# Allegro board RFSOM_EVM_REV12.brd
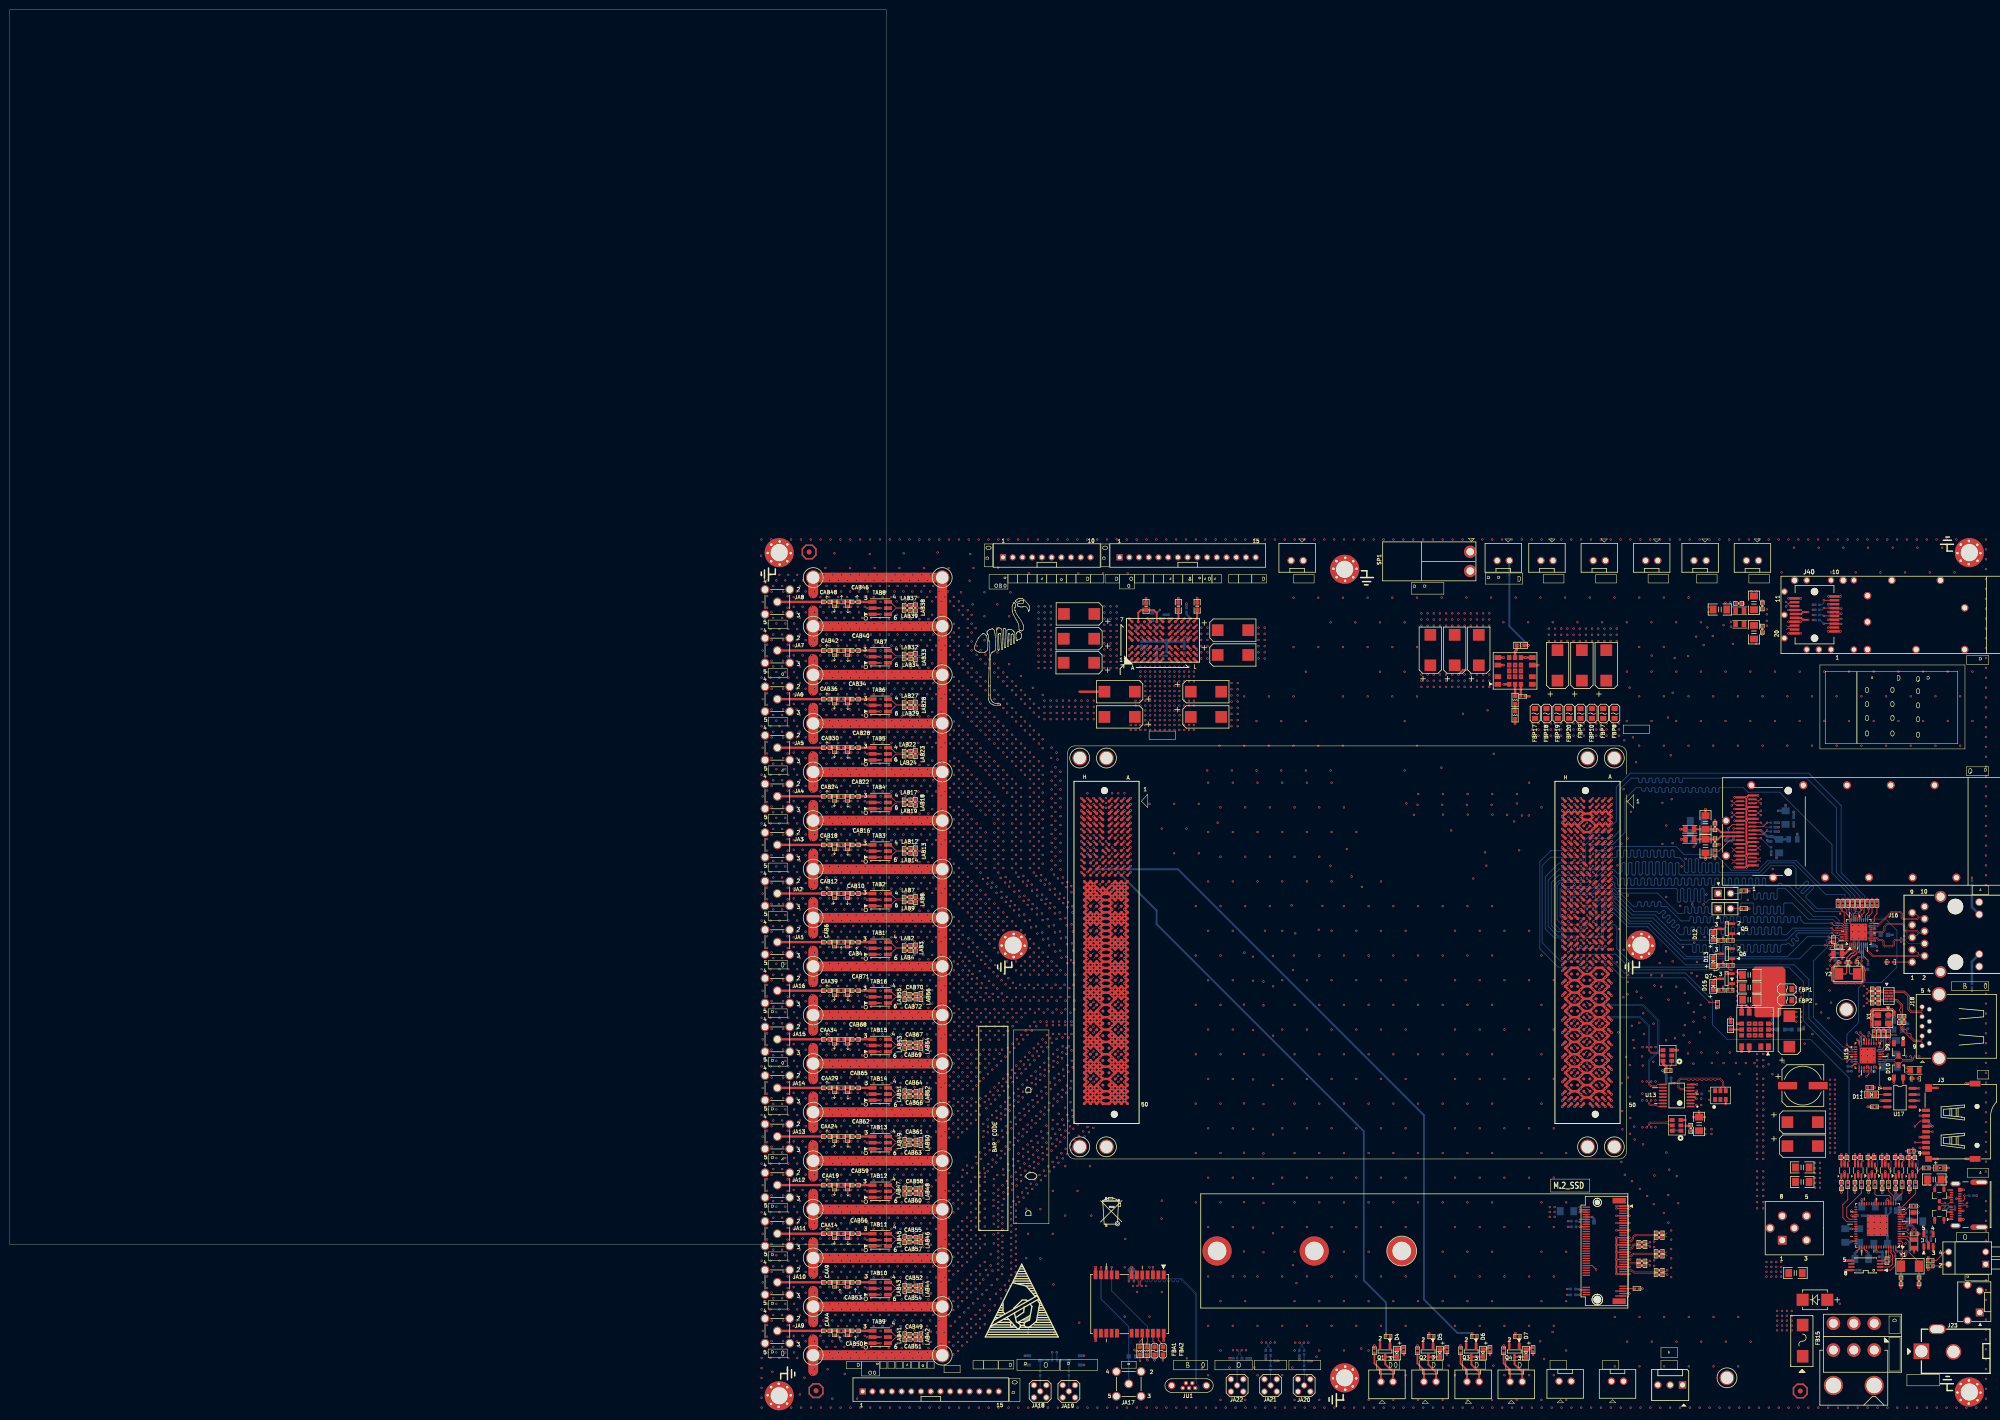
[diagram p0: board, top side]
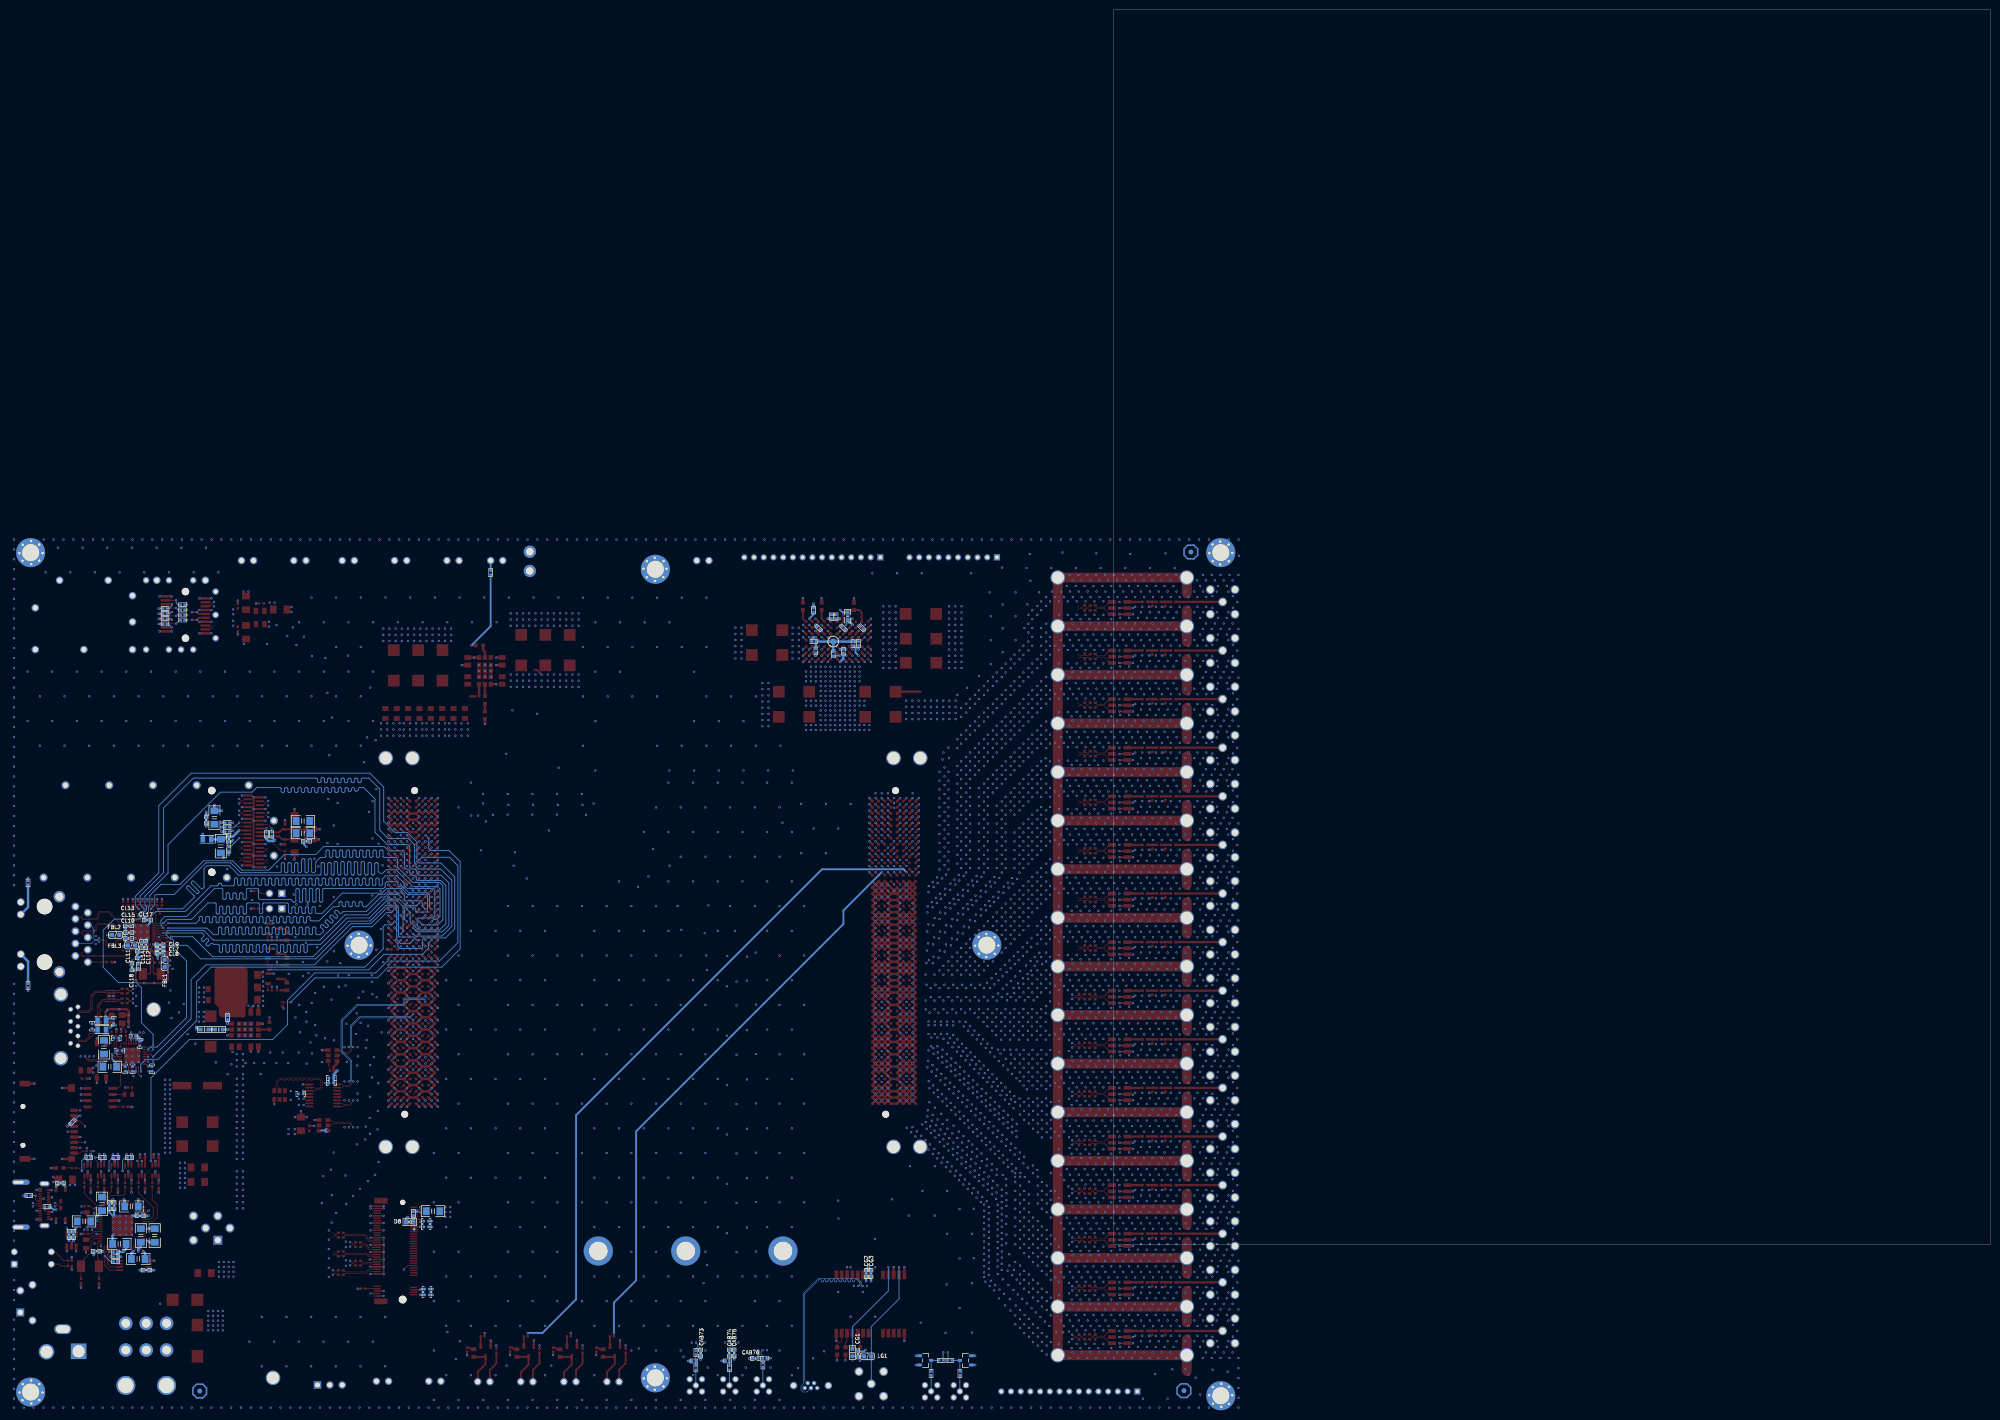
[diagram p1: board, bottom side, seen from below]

Outline 180.34 x 254 mm; copper layers: TOP, GND02, ART03, GND04, ART05, GND06, POWER07, POWER08, GND09, ART10, GND11, BOTTOM. Coordinates in mm from the lower left corner of the outline.
Outline path: 0,254 180.34,254 180.34,0 0,0 0,254

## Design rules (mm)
constraint set DEFAULT: min track width 0.173
net group BANK128_MGT_CLK1: nets BANK128_MGT_CLK1_N BANK128_MGT_CLK1_P
net group BANK128_MGT_RX0_: nets BANK128_MGT_RX0_N BANK128_MGT_RX0_P
net group BANK128_MGT_RX1_: nets BANK128_MGT_RX1_N BANK128_MGT_RX1_P
net group BANK128_MGT_RX2_: nets BANK128_MGT_RX2_N BANK128_MGT_RX2_P
net group BANK128_MGT_RX3_: nets BANK128_MGT_RX3_N BANK128_MGT_RX3_P
net group BANK128_MGT_TX0_: nets BANK128_MGT_TX0_N BANK128_MGT_TX0_P
net group BANK128_MGT_TX1_: nets BANK128_MGT_TX1_N BANK128_MGT_TX1_P
net group BANK128_MGT_TX2_: nets BANK128_MGT_TX2_N BANK128_MGT_TX2_P
net group BANK128_MGT_TX3_: nets BANK128_MGT_TX3_N BANK128_MGT_TX3_P
net group BANK129_MGT_RX0_: nets BANK129_MGT_RX0_N BANK129_MGT_RX0_P
net group BANK129_MGT_TX0_: nets BANK129_MGT_TX0_N BANK129_MGT_TX0_P
net group BANK505_MGT_CLK0_: nets BANK505_MGT_CLK0_N BANK505_MGT_CLK0_P
net group BANK505_MGT_CLK2_: nets BANK505_MGT_CLK2_N BANK505_MGT_CLK2_P
net group BANK505_MGT_RX0_N: nets BANK505_MGT_RX0_N N2236203120
net group BANK505_MGT_RX0_P: nets BANK505_MGT_RX0_P N2236203121
net group BANK505_MGT_RX1_N: nets BANK505_MGT_RX1_N N2236203114
net group BANK505_MGT_RX1_P: nets BANK505_MGT_RX1_P N2236203115
net group BANK505_MGT_TX0_N: nets BANK505_MGT_TX0_N N2236203123
net group BANK505_MGT_TX0_P: nets BANK505_MGT_TX0_P N2236203124
net group BANK505_MGT_TX1_N: nets BANK505_MGT_TX1_N N2236203117
net group BANK505_MGT_TX1_P: nets BANK505_MGT_TX1_P N2236203118
net group CLK_100M_: nets CLK_100M_N CLK_100M_P
net group CLKIN0_: nets CLKIN0_N CLKIN0_P
net group DIFFPAIR11: nets N22696463 N22696580
net group DIFFPAIR12: nets N22696156 N22696283
net group DIFFPAIR13: nets N22697841 N22697954
net group DIFFPAIR14: nets N22697544 N22697657
net group DIFFPAIR15: nets N22699217 N22699330
net group DIFFPAIR16: nets N22698936 N22699049
net group DIFFPAIR17: nets N22700663 N22700802
net group DIFFPAIR18: nets N22700324 N22700437
net group DIFFPAIR19: nets N22692224 N22692315
net group DIFFPAIR20: nets N22692505 N22692596
net group DIFFPAIR21: nets N22693543 N22693634
net group DIFFPAIR22: nets N22693824 N22693915
net group DIFFPAIR23: nets N22694836 N22694927
net group DIFFPAIR24: nets N22545864 N22545955
net group DIFFPAIR25: nets N22695117 N22695208
net group DIFFPAIR26: nets N22546147 N22546240
net group DU: nets DU+ DU-
net group GPS_USB_D: nets GPS_USB_DN GPS_USB_DP
net group M2_DEV_CLKN: nets M2_DEV_CLKN N223618380
net group M2_DEV_CLKP: nets M2_DEV_CLKP N223618460
net group N22536481: nets N22536481 N22536506
net group RX_00: nets RX_00_N RX_00_P
net group RX_01: nets RX_01_N RX_01_P
net group RX_02: nets RX_02_N RX_02_P
net group RX_03: nets RX_03_N RX_03_P
net group RX_04: nets RX_04_N RX_04_P
net group RX_05: nets RX_05_N RX_05_P
net group RX_06: nets RX_06_N RX_06_P
net group RX_07: nets RX_07_N RX_07_P
net group SYS_CLK_OUT_: nets SYS_CLK_OUT_N SYS_CLK_OUT_P
net group SYSREF_IN_: nets SYSREF_IN_N SYSREF_IN_P
net group TX_00: nets TX_00_N TX_00_P
net group TX_01: nets TX_01_N TX_01_P
net group TX_02: nets TX_02_N TX_02_P
net group TX_03: nets TX_03_N TX_03_P
net group TX_04: nets TX_04_N TX_04_P
net group TX_05: nets TX_05_N TX_05_P
net group TX_06: nets TX_06_N TX_06_P
net group TX_07: nets TX_07_N TX_07_P
net group +1.8V: nets N22536187
net group POWER: nets ZQSFP_VCC ZQSFP_VCCRX ZQSFP_VCCTX
net group RF: nets N22545929 N22545941 N22545947 N22545953 N22546214 N22546226 N22546232 N22546238 N22692289 N22692291 N22692307 N22692313 N22692570 N22692582 N22692588 N22692594 N22693600 N22693620 N22693626 N22693632 N22693889 N22693901 N22693907 N22693913 N22694901 N22694903 N22694919 N22694925 N22695182 N22695184 N22695200 N22695206 N22696251 N22696263 N22696269 N22696275 N22696550 N22696562 N22696568 N22696574 N22697619 N22697639 N22697645 N22697651 N22697916 N22697918 N22697942 N22697948 N22699019 N22699033 N22699037 N22699043 N22699300 N22699302 N22699318 N22699324 N22700407 N22700409 N22700425 N22700431 N22700760 N22700762 N22700790 N22700796
net group USB_90: nets BANK505_MGT_RX2_N BANK505_MGT_RX2_P BANK505_MGT_TX2_N BANK505_MGT_TX2_P N223630967 N223630968 USB_DM USB_DP USB_RX_N USB_RX_P USB_TX_N USB_TX_P

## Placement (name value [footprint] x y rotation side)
C1  0.1uF/25V/X7R/10%  [C0402]  382.48 12.04 270 top
C2  0.1uF/25V/X7R/10%  [C0402]  382.98 17.81 0 top
C3  0.1uF/25V/X7R/10%  [C0402]  390.86 12.04 270 top
C4  0.1uF/25V/X7R/10%  [C0402]  391.37 17.81 0 top
C5  0.1uF/25V/X7R/10%  [C0402]  388.06 12.04 270 top
C6  0.1uF/25V/X7R/10%  [C0402]  388.57 17.81 0 top
C7  0.1uF/25V/X7R/10%  [C0402]  385.27 12.04 270 top
C8  0.1uF/25V/X7R/10%  [C0402]  385.78 17.81 0 top
C9  47uF/6.3V/X5R/20%  [C1206]  380.54 1.78 90 bottom
C10  47uF/6.3V/X5R/20%  [C1206]  384.96 0.05 0 bottom
C11  18PF/25V/X5R/20%  [C0402]  389.15 -7.57 270 top
C12  0.1uF/25V/X7R/10%  [C0402]  379.68 12.04 270 top
C13  0.1uF/25V/X7R/10%  [C0402]  380.19 17.81 0 top
C14  18PF/25V/X5R/20%  [C0402]  392.86 -7.57 270 top
C15  22UF/25V/X5R/20%  [C1206]  396.01 13.31 0 top
C16  0.47uF/6.3V/X5R/20%  [C0402]  397.05 12.57 0 bottom
C17  0.1uF/25V/X7R/10%  [C0402]  376.89 12.04 270 top
C18  0.1uF/25V/X7R/10%  [C0402]  377.4 17.81 0 top
C19  47uF/6.3V/X5R/20%  [C1206]  382.47 7.75 0 bottom
C20  47uF/6.3V/X5R/20%  [C1206]  377.7 1.78 270 bottom
C21  47uF/6.3V/X5R/20%  [C0402]  387.02 7.9 270 bottom
C22  47uF/6.3V/X5R/20%  [C0402]  386.05 7.9 270 bottom
C23  22UF/25V/X5R/20%  [C1206]  392.23 4.68 180 bottom
C24  0.47uF/6.3V/X5R/20%  [C0402]  394.41 1.98 270 bottom
C25  47uF/6.3V/X5R/20%  [C1206]  388.54 8.28 90 bottom
C26  47uF/6.3V/X5R/20%  [C1206]  381.08 -3.05 0 bottom
C27  4.7uF/6.3V/X5R/20%  [C0402]  389.69 -1.47 0 bottom
C28  0.47uF/6.3V/X5R/20%  [C0402]  380.7 5.86 0 bottom
C29  0.1uF/25V/X7R/10%  [C0402]  395.33 1.98 270 bottom
C30  0.47uF/10V/X5R/20%  [C0402]  379.45 -5.35 0 bottom
C31  22uF/25V,X5R/20%  [C1206]  347.19 84.56 0 bottom
C32  0.1uF/25V/,X7R/10%  [C0402]  346.48 82.88 0 bottom
C33  22uF/25V,X5R/20%  [C1206]  348.93 81.89 270 top
C34  0.1uF/25V/,X7R/10%  [C0402]  350.88 82.78 270 top
C35  22uF/25V,X5R/20%  [C1206]  364.08 81.9 270 bottom
C36  0.1uF/25V/,X7R/10%  [C0402]  362.43 83.36 270 bottom
C37  22uF/25V,X5R/20%  [C1206]  348.93 86.77 90 top
C38  0.1uF/25V/,X7R/10%  [C0402]  350.88 85.88 90 top
C39  22uF/25V,X5R/20%  [C1206]  365.4 87.77 90 bottom
C40  0.1uF/25V/,X7R/10%  [C0402]  367.08 87.26 90 bottom
C41  22uF/25V,X5R/20%  [C1206]  347.6 24.73 90 top
C42  0.1uF/25V/,X7R/10%  [C0402]  345.89 23.84 90 top
C43  22uF/25V,X5R/20%  [C1206]  351.89 130.58 180 top
C44  0.1uF/25V/,X7R/10%  [C0402]  355.75 131.83 0 top
C45  22uF/25V,X5R/20%  [C1206]  358.9 131.96 90 top
C46  0.1uF/25V/,X7R/10%  [C0402]  360.61 131.32 90 top
C47  22uF/25V,X5R/20%  [C1206]  358.9 125.91 270 top
C48  0.1uF/25V/,X7R/10%  [C0402]  360.61 126.54 270 top
C53  CAP,0.1UF,DC25V,0402,X5R  [C0402-BGA]  387.06 58.03 180 top
C57  CAP,27pF,DC25V,0402,X5R  [C0402-BGA]  379.36 57.9 180 top
C58  CAP,27pF,DC25V,0402,X5R  [C0402-BGA]  377.18 57.92 0 top
C68  0.1uF/25V/X7R/10%  [C0402]  339.39 2.31 0 top
C69  0.1uF/25V/X7R/10%  [C0402]  339.39 1.37 0 top
C70  0.1uF/25V/X7R/10%  [C0402]  335.84 0.39 0 top
C71  0.1uF/25V/X7R/10%  [C0402]  335.84 -0.55 0 top
C72  0.1uF/25V/X7R/10%  [C0402]  339.39 -1.53 0 top
C73  0.1uF/25V/X7R/10%  [C0402]  339.39 -2.47 0 top
C74  0.1uF/25V/X7R/10%  [C0402]  335.84 -3.46 0 top
C75  0.1uF/25V/X7R/10%  [C0402]  335.84 -4.4 0 top
C76  0.1uF/25V/X7R/10%  [C0402]  339.39 -5.38 0 top
C77  0.1uF/25V/X7R/10%  [C0402]  339.39 -6.32 0 top
C78  0.1uF/25V/,X7R/10%  [C0402-BGA]  347.63 30.91 180 bottom
C79  10uF/25V/X5R/20%  [C1206]  347.19 87.07 0 bottom
C80  0.1uF/25V/,X7R/10%  [C0402-BGA]  321.67 -10.44 180 bottom
C81  0.1uF/25V/,X7R/10%  [C0402-BGA]  321.67 -9.25 180 bottom
C84  0.1uF/25V/,X7R/10%  [C1206]  320.42 6.78 180 bottom
C85  0.1uF/25V/,X7R/10%  [C0402-BGA]  321.84 3.56 180 bottom
C86  0.1uF/25V/,X7R/10%  [C0402-BGA]  321.84 4.72 180 bottom
C87  0.1uF/25V/,X7R/10%  [C0402-BGA]  390.56 44.85 90 bottom
C88  0.1uF/25V/,X7R/10%  [C0402]  389.78 46.23 270 top
C89  0.1uF/25V/,X7R/10%  [C0402]  388.8 46.23 270 top
C90  4.7UF/25V/X5R/20%  [C1206]  386.94 36.5 0 bottom
C91  0.1uF/25V/,X7R/10%  [C0402-BGA]  392.18 34.06 180 top
C92  0.1uF/25V/,X7R/10%  [C0402]  383.87 52.53 180 top
C93  10uF/25V/X5R/10%  [C1206]  388.14 40.51 270 bottom
C94  0.1uF/25V/,X7R/10%  [C0402-BGA]  385.6 42.44 180 bottom
C95  0.1uF/25V/,X7R/10%  [C0402]  383.87 51.59 180 top
C96  0.1uF/25V/,X7R/10%  [C0402]  383.87 49.58 180 top
C97  0.1uF/25V/,X7R/10%  [C0402]  383.87 50.52 180 top
C98  0.47UF/25V/X5R/10%  [C0402-BGA]  386.13 45.9 90 bottom
C101  0.1uF/25V/,X7R/10%  [C0402-BGA]  380.8 41.3 270 bottom
C102  0.1uF/25V/,X7R/10%  [C0402-BGA]  382.27 36.07 90 bottom
C103  0.1uF/25V/,X7R/10%  [C0402-BGA]  378.21 36.08 270 bottom
C104  0.1uF/25V/,X7R/10%  [C0402-BGA]  383.74 36.06 90 bottom
C105  100pF/10V/X5R/20%  [C0603]  233.82 131.22 90 top
C106  100pF/10V/X5R/20%  [C0603]  240.46 131.24 90 top
C107  100pF/10V/X5R/20%  [C0603]  244.33 131.24 90 top
C108  22UF/25V/X5R/20%  [C1206]  367.44 -5.94 0 top
C109  22UF/25V/X5R/20%  [C1206]  368.83 12.8 0 top
C110  22UF/25V/X5R/20%  [C1206]  368.83 15.79 0 top
C288  1uF/25V/,X5R/10%  [C0402-BGA]  341.34 33.11 0 bottom
C289  0.1uF/25V/,X7R/10%  [C0402-BGA]  341.34 34.2 0 bottom
C290  0.1uF/25V/,X7R/10%  [C0402-BGA]  384.88 39.82 180 bottom
CAA4  0.1uF/25V/X7R/10%  [0402C]  168.1 -17.85 0 top
CAA9  0.1uF/25V/X7R/10%  [0402C]  168.1 -7.85 0 top
CAA14  0.1uF/25V/X7R/10%  [0402C]  168.1 2.15 0 top
CAA19  0.1uF/25V/X7R/10%  [0402C]  168.1 12.15 0 top
CAA24  0.1uF/25V/X7R/10%  [0402C]  168.1 22.15 0 top
CAA29  0.1uF/25V/X7R/10%  [0402C]  168.1 32.15 0 top
CAA34  0.1uF/25V/X7R/10%  [0402C]  168.1 42.15 0 top
CAA39  0.1uF/25V/X7R/10%  [0402C]  168.1 52.15 0 top
CAB4  0.1uF/25V/X7R/10%  [0402C]  173.97 62.15 180 top
CAB6  0.1uF/25V/X7R/10%  [0402C]  168.1 62.15 180 top
CAB10  0.1uF/25V/X7R/10%  [0402C]  173.97 72.15 180 top
CAB12  0.1uF/25V/X7R/10%  [0402C]  168.1 72.15 180 top
CAB16  0.1uF/25V/X7R/10%  [0402C]  173.97 82.15 180 top
CAB18  0.1uF/25V/X7R/10%  [0402C]  168.1 82.15 180 top
CAB22  0.1uF/25V/X7R/10%  [0402C]  173.97 92.15 180 top
CAB24  0.1uF/25V/X7R/10%  [0402C]  168.1 92.15 180 top
CAB28  0.1uF/25V/X7R/10%  [0402C]  173.97 102.15 180 top
CAB30  0.1uF/25V/X7R/10%  [0402C]  168.1 102.15 180 top
CAB34  0.1uF/25V/X7R/10%  [0402C]  173.97 112.15 180 top
CAB36  0.1uF/25V/X7R/10%  [0402C]  168.1 112.15 180 top
CAB40  0.1uF/25V/X7R/10%  [0402C]  173.97 122.15 180 top
CAB42  0.1uF/25V/X7R/10%  [0402C]  168.1 122.15 180 top
CAB46  0.1uF/25V/X7R/10%  [0402C]  173.97 132.15 180 top
CAB48  0.1uF/25V/X7R/10%  [0402C]  168.1 132.15 180 top
CAB49  0.1uF/25V/X7R/10%  [0402C]  185.83 -18.57 180 top
CAB50  0.1uF/25V/X7R/10%  [0402C]  173.97 -17.85 180 top
CAB51  0.1uF/25V/X7R/10%  [0402C]  185.83 -19.59 180 top
CAB52  0.1uF/25V/X7R/10%  [0402C]  185.83 -8.57 180 top
CAB53  0.1uF/25V/X7R/10%  [0402C]  173.97 -7.85 180 top
CAB54  0.1uF/25V/X7R/10%  [0402C]  185.83 -9.59 180 top
CAB55  0.1uF/25V/X7R/10%  [0402C]  185.83 1.43 180 top
CAB56  0.1uF/25V/X7R/10%  [0402C]  173.97 2.15 180 top
CAB57  0.1uF/25V/X7R/10%  [0402C]  185.83 0.41 180 top
CAB58  0.1uF/25V/X7R/10%  [0402C]  185.83 11.43 180 top
CAB59  0.1uF/25V/X7R/10%  [0402C]  173.97 12.15 180 top
CAB60  0.1uF/25V/X7R/10%  [0402C]  185.83 10.41 180 top
CAB61  0.1uF/25V/X7R/10%  [0402C]  185.83 21.43 180 top
CAB62  0.1uF/25V/X7R/10%  [0402C]  173.97 22.15 180 top
CAB63  0.1uF/25V/X7R/10%  [0402C]  185.83 20.41 180 top
CAB64  0.1uF/25V/X7R/10%  [0402C]  185.83 31.43 180 top
CAB65  0.1uF/25V/X7R/10%  [0402C]  173.97 32.15 180 top
CAB66  0.1uF/25V/X7R/10%  [0402C]  185.83 30.41 180 top
CAB67  0.1uF/25V/X7R/10%  [0402C]  185.83 41.43 180 top
CAB68  0.1uF/25V/X7R/10%  [0402C]  173.97 42.15 180 top
CAB69  0.1uF/25V/X7R/10%  [0402C]  185.83 40.41 180 top
CAB70  0.1uF/25V/X7R/10%  [0402C]  185.83 51.43 180 top
CAB71  0.1uF/25V/X7R/10%  [0402C]  173.97 52.15 180 top
CAB72  0.1uF/25V/X7R/10%  [0402C]  185.83 50.41 180 top
CAB73  0.1uF/25V/X7R/10%  [0402C]  265.35 -22.42 90 bottom
CAB74  0.1uF/25V/X7R/10%  [0402C]  259.45 -22.4 90 bottom
CAB75  0.1uF/25V/X7R/10%  [0402C]  258.46 -22.4 90 bottom
CAB76  0.1uF/25V/X7R/10%  [0402C]  254.05 -23.52 180 bottom
CG1  0.01uF/16V/X5R/20%  [0402C]  233 -22.58 90 bottom
CG2  0.1uF/25V/,X7R/10%  [0402C]  231.32 -6.03 270 bottom
CG3  47pF/16V/X7R/20%  [0402C]  230.3 -6.03 270 bottom
CIN1  22uF/25V/X5R/20%  [7343-43]  220 119.63 180 top
CIN2  22uF/25V/X5R/20%  [7343-43]  220.01 124.57 180 top
CIN3  22uF/25V/X5R/20%  [7343-43]  220.05 129.68 180 top
CIN4  22uF/25V/X5R/20%  [7343-43]  251.69 126.34 0 top
CIN5  100uF/25V/X5R/20%  [7343-43]  251.69 121.23 0 top
CIN6  22uF/25V/X5R/20%  [7343-43]  368.91 20.17 0 top
CIN7  22uF/25V/X5R/20%  [7343-43]  366.18 43.76 90 top
CIN8  22uF/25V/X5R/20%  [7343-43]  368.91 25.1 0 top
CIN9  22uF/25V/X5R/20%  [7343-43]  297.31 122.23 90 top
CIN10  22uF/25V/X5R/20%  [7343-43]  302.28 122.23 90 top
CIN11  22uF/25V/X5R/20%  [7343-43]  292.31 122.23 90 top
CL7  10uF/10V/X5R/10%  [0402C]  376.59 60.72 180 bottom
CL8  0.01uF/10V/X5R/10%  [0402C]  376.59 59.86 180 bottom
CL9  0.1uF/16V/X7R/10%  [0402C]  376.59 61.61 180 bottom
CL10  0.1uF/16V/X7R/10%  [0402C]  383.1 62.89 0 bottom
CL11  0.1uF/16V/X7R/10%  [0402C]  381.31 59.56 90 bottom
CL12  10uF/10V/X7R/10%  [0402C]  379.5 61.63 270 bottom
CL13  0.1uF/16V/X7R/10%  [0402C]  383.12 65.48 0 bottom
CL14  0.1uF/16V/X7R/10%  [0402C]  380.41 61.65 270 bottom
CL15  1uF/16V/X7R/10%  [0402C]  383.03 64.1 0 bottom
CL17  1uF/16V/X7R/10%  [0402C]  379.18 66.69 0 bottom
CL18  0.1uF/16V/X7R/10%  [0402C]  382.37 57.06 90 bottom
COUT1  100uF/16V/X5R/20%  [7343-43]  246.15 108.48 0 top
COUT2  100uF/16V/X5R/20%  [7343-43]  228.38 113.67 180 top
COUT3  100uF/16V/X5R/20%  [7343-43]  228.38 108.48 180 top
COUT4  100uF/16V/X5R/20%  [7343-43]  246.15 113.67 0 top
COUT5  100nF/10V/X5R/20%  [C0603]  235.1 129.21 90 bottom
COUT9  220uF/4V/X5R/20%  [C1206]  357.94 50.29 180 top
COUT10  220uF/4V/X5R/20%  [C1206]  357.94 55.4 180 top
COUT11  220uF/4V/X5R/20%  [C1206]  357.94 52.81 180 top
COUT12  220uF/10V/X5R/20%  [7343-43]  323.49 119.09 90 top
COUT13  220uF/10V/X5R/20%  [7343-43]  318.48 119.09 90 top
COUT14  220uF/10V/X5R/20%  [7343-43]  328.5 119.09 90 top
D1  SCHOTTKY,BAT54S  [SOT23]  397.04 9.99 270 top
D2  SCHOTTKY,BAT54S  [SOT23]  397.04 6.3 90 top
D3  LED,GREEN,0603  [LED-0603]  397.23 15.67 180 top
D4  LED  [0603LED]  285.43 -22.42 270 top
D5  LED  [0603LED]  294.3 -22.42 270 top
D6  LED  [0603LED]  303.16 -22.42 270 top
D7  LED  [0603LED]  312.02 -22.42 270 top
D8  GREEN  [0603LED]  325.22 4.52 0 bottom
D9  BAT54S  [SO-G3]  388.64 40.06 0 top
D10  BAT54S  [SO-G3]  388.64 35.56 180 top
D11  RED  [0603LED]  383.11 30.78 0 top
D12  GREEN  [0603LED]  350.49 63.29 90 top
D13  RED  [0603LED]  350.49 58.16 90 top
D14  SCHOTTKY,BAT54S  [SOT23]  210.86 -23.92 0 bottom
D15  YELLOW  [0603LED]  350.49 53.03 90 top
D16  SCHOTTKY,BAT54S  [SOT23]  219.08 -23.92 180 bottom
D19  SMBJ22A  [SMB]  371.45 -11.46 180 top
EC1  16SVPK330M  [EC-E7]  368.96 32.61 0 top
FB1  BLM18PG181SN1  [FB0805]  391.82 0.05 90 top
FB2  BLM18PG181SN1  [FB0805]  391.73 5.63 270 top
FB3  BLM21PG121SN1D  [FB0805]  345.69 83.29 0 top
FB4  BLM21PG121SN1D  [FB0805]  366.92 83.29 180 bottom
FB5  BLM21PG121SN1D  [FB0805]  345.69 85.37 0 top
FB6  BLM21PG121SN1D  [FB0805]  355.99 130.31 0 top
FB7  BLM21PG121SN1D  [FB0805]  355.99 127.56 0 top
FB9  4.7uH 400mA  [FB0805]  376.14 59.79 0 top
FB12  BLM21PG121SN1D  [FB0805]  388.57 44.15 0 bottom
FB13  BLM21PG121SN1D  [FB0805]  388.57 45.97 0 bottom
FB14  BLM21PG121SN1D  [FB0805]  392.02 35.76 0 top
FB15  PPTC_10A  [7343FUSE]  368.91 -19.86 90 top
FBA1  BLM18PG221SN1  [0603L]  235.56 -21.97 90 top
FBA2  BLM18PG221SN1  [0603L]  237.27 -21.97 90 top
FBL1  BEAD  [0603L]  375.66 57.77 90 bottom
FBL2  BEAD  [0603L]  385.73 63.64 0 bottom
FBL3  BEAD  [0603L]  382.48 61.46 0 bottom
FBP1  BLM21PG121SN1  [0805L]  365.67 52.48 180 top
FBP2  BLM21PG121SN1  [0805L]  365.67 50.19 180 top
FBP7  BLM21PG121SN1  [0805L]  327.88 109.19 90 top
FBP8  BLM21PG121SN1  [0805L]  330.22 109.19 90 top
FBP9  BLM21PG121SN1  [0805L]  323.21 109.19 90 top
FBP10  BLM21PG121SN1  [0805L]  325.55 109.19 90 top
FBP17  BLM21PG121SN1  [0805L]  313.86 109.19 90 top
FBP18  BLM21PG121SN1  [0805L]  316.2 109.19 90 top
FBP19  BLM21PG121SN1  [0805L]  318.54 109.19 90 top
FBP20  BLM21PG121SN1  [0805L]  320.87 109.19 90 top
H7  HOLE  [HOLE_D2_5]  191.87 -12.85 0 top
H8  HOLE  [HOLE_D2_5]  191.87 -22.85 270 top
H9  HOLE  [HOLE_D2_5]  191.87 -2.85 270 top
H10  HOLE  [HOLE_D2_5]  191.87 107.15 270 top
H11  HOLE  [HOLE_D2_5]  165.33 107.15 270 top
H12  HOLE  [HOLE_D2_5]  165.33 117.15 270 top
H13  HOLE  [HOLE_D2_5]  191.87 137.15 270 top
H14  HOLE  [HOLE_D2_5]  165.33 137.15 270 top
H15  HOLE  [HOLE_D2_5]  165.33 127.15 270 top
H16  HOLE  [HOLE_D2_5]  191.87 37.15 270 top
H17  HOLE  [HOLE_D2_5]  165.33 27.15 270 top
H18  HOLE  [HOLE_D2_5]  191.87 57.15 270 top
H19  HOLE  [HOLE_D2_5]  165.33 57.15 270 top
H20  HOLE  [HOLE_D2_5]  165.33 97.15 270 top
H21  HOLE  [HOLE_D2_5]  191.87 97.15 270 top
H22  HOLE  [HOLE_D2_5]  165.33 87.15 270 top
H23  HOLE  [HOLE_D2_5]  191.87 127.15 270 top
H24  HOLE  [HOLE_D2_5]  191.87 117.15 270 top
H25  HOLE  [HOLE_D2_5]  191.87 7.15 270 top
H26  HOLE  [HOLE_D2_5]  165.33 7.15 270 top
H27  HOLE  [HOLE_D2_5]  191.87 47.15 270 top
H28  HOLE  [HOLE_D2_5]  165.33 47.15 270 top
H29  HOLE  [HOLE_D2_5]  165.33 37.15 270 top
H30  HOLE  [HOLE_D2_5]  191.87 87.15 270 top
H31  HOLE  [HOLE_D2_5]  191.87 77.15 270 top
H32  HOLE  [HOLE_D2_5]  165.33 77.15 270 top
H33  HOLE  [HOLE_D2_5]  165.33 67.15 270 top
H34  HOLE  [HOLE_D2_5]  191.87 67.15 270 top
H35  HOLE  [HOLE_D2_5]  165.33 -2.85 270 top
H36  HOLE  [HOLE_D2_5]  165.33 -12.85 270 top
H37  HOLE  [HOLE_D2_5]  165.33 -22.85 0 top
H38  HOLE  [HOLE_D2_5]  191.87 27.15 270 top
H39  HOLE  [HOLE_D2_5]  165.33 17.15 270 top
H40  HOLE  [HOLE_D2_5]  191.87 17.15 270 top
H41  -  [HOLE]  274.68 138.86 0 top
H42  -  [HOLE]  403.21 -30.43 180 top
H43  -  [HOLE]  274.68 -27.51 270 top
H44  -  [HOLE]  158.33 -31.19 90 top
H45  -  [HOLE]  335.64 61.52 270 top
H46  -  [HOLE]  206.48 61.52 270 top
H47  -  [HOLE]  158.33 142.29 270 top
H48  -  [HOLE]  403.21 142.29 180 top
J1  LPAM_50_01_0_L_08_2_K_TR  [LPAM_50_01_TR]  225.25 60.02 270 top
J2  LPAM_50_01_0_L_08_2_K_TR  [LPAM_50_01_TR]  324.22 60.02 270 top
J3  -  [TF01A]  394.31 27.53 90 top
J4  USB-TYPEC  [2012670005]  400.4 8.12 90 top
J5  -  [HX-TJC3-2PIN-WHITE]  283.38 -28.31 180 top
J6  -  [HX-TJC3-2PIN-WHITE]  292.25 -28.31 180 top
J7  -  [HX-TJC3-2PIN-WHITE]  301.11 -28.31 180 top
J8  -  [HX-TJC3-2PIN-WHITE]  309.98 -28.31 180 top
J9  JST_2p0_10P  [SIP10_2-0MM_S]  213.38 141.32 0 top
J10  JST_2p0_15P  [SIP15_2-0MM_S]  242.37 141.32 0 top
J11  JST_2p0_15P  [SIP15_2-0MM_S]  189.51 -30.31 0 top
J12  FS1-Z38-20Z6-20  [QSFP28_CON]  365.95 84.93 90 top
J13  U95-T1A1-101A  [U95-T1N1-101A]  365.95 76.53 270 top
J16  -  [HR911130C]  391.46 58.03 270 top
J17  M.2 SSD socket 3  [M2_2422]  331.95 7.85 90 top
J18  -  [USB3-A]  396.99 44.82 90 top
J19  -  [HX-TJC3-2PIN-WHITE]  330.82 -28.21 180 top
J20  -  [HX-TJC3-2PIN-WHITE]  320.05 -28.21 180 top
J21  -  [HX-TJC3-2PIN-WHITE]  358.59 140.65 0 top
J22  -  [HX-TJC3-2PIN-WHITE]  327.08 140.65 0 top
J23  POWER_JACK_ADAPTER  [POWERA]  393.35 -22.06 0 top
J24  -  [HX-TJC3-2PIN-WHITE]  264.9 140.65 0 top
J25  -  [HX-TJC3-2PIN-WHITE]  347.82 140.65 0 top
J26  POWER HEADER-6P-4P2MM  [POWER_HEADER-6P-4P2MM]  383.64 -21.79 270 top
J27  -  [HX-TJC3-2PIN-WHITE]  337.85 140.65 0 top
J28  -  [HX-TJC3-2PIN-WHITE]  316.31 140.65 0 top
J32  -  [022112032]  344.2 -28.98 270 top
J40  74441-0010  [SFP_MODULE]  375.46 126.08 180 top
JA1  SMB  [SMB_RF]  157.95 62.15 270 top
JA2  SMB  [SMB_RF]  157.95 72.15 270 top
JA3  SMB  [SMB_RF]  157.95 82.15 270 top
JA4  SMB  [SMB_RF]  157.95 92.15 270 top
JA5  SMB  [SMB_RF]  157.95 102.15 270 top
JA6  SMB  [SMB_RF]  157.95 112.15 270 top
JA7  SMB  [SMB_RF]  157.95 122.15 270 top
JA8  SMB  [SMB_RF]  157.95 132.15 270 top
JA9  SMB  [SMB_RF]  157.95 -17.85 270 top
JA10  SMB  [SMB_RF]  157.95 -7.85 270 top
JA11  SMB  [SMB_RF]  157.95 2.15 270 top
JA12  SMB  [SMB_RF]  157.95 12.15 270 top
JA13  SMB  [SMB_RF]  157.95 22.15 270 top
JA14  SMB  [SMB_RF]  157.95 32.15 270 top
JA15  SMB  [SMB_RF]  157.95 42.15 270 top
JA16  SMB  [SMB_RF]  157.95 52.15 270 top
JA17  SMB  [SMB_RF]  230.25 -28.76 270 top
JA18  MMCX  [MMCX-TH1]  213.29 -30.29 270 top
JA19  MMCX  [MMCX-TH1]  219.21 -30.29 270 top
JA20  MMCX  [MMCX-TH1]  266.34 -27.8 0 top
JA21  MMCX  [MMCX-TH1]  259.45 -27.8 0 top
JA22  MMCX  [MMCX-TH1]  252.55 -27.8 0 top
JFA6  -  [HX-TJC3-2PIN-WHITE]  307.31 140.65 0 top
JU1  -  [USB-MICRO-VER]  242.66 -29.11 180 top
LAB2  0.1uF/25V/X7R/10%  [0402C]  184.67 61.43 0 top
LAB3  NC  [0402C]  186.34 60.92 90 top
LAB4  0.1uF/25V/X7R/10%  [0402C]  184.67 60.41 0 top
LAB7  0.1uF/25V/X7R/10%  [0402C]  184.67 71.43 0 top
LAB8  NC  [0402C]  186.34 70.92 90 top
LAB9  0.1uF/25V/X7R/10%  [0402C]  184.67 70.41 0 top
LAB12  0.1uF/25V/X7R/10%  [0402C]  184.67 81.43 0 top
LAB13  NC  [0402C]  186.34 80.92 90 top
LAB14  0.1uF/25V/X7R/10%  [0402C]  184.67 80.41 0 top
LAB17  0.1uF/25V/X7R/10%  [0402C]  184.67 91.43 0 top
LAB18  NC  [0402C]  186.34 90.92 90 top
LAB19  0.1uF/25V/X7R/10%  [0402C]  184.67 90.41 0 top
LAB22  0.1uF/25V/X7R/10%  [0402C]  184.67 101.43 0 top
LAB23  NC  [0402C]  186.34 100.92 90 top
LAB24  0.1uF/25V/X7R/10%  [0402C]  184.67 100.41 0 top
LAB27  0.1uF/25V/X7R/10%  [0402C]  184.67 111.43 0 top
LAB28  NC  [0402C]  186.34 110.92 90 top
LAB29  0.1uF/25V/X7R/10%  [0402C]  184.67 110.41 0 top
LAB32  0.1uF/25V/X7R/10%  [0402C]  184.67 121.43 0 top
LAB33  NC  [0402C]  186.34 120.92 90 top
LAB34  0.1uF/25V/X7R/10%  [0402C]  184.67 120.41 0 top
LAB37  0.1uF/25V/X7R/10%  [0402C]  184.67 131.43 0 top
LAB38  NC  [0402C]  186.34 130.92 90 top
LAB39  0.1uF/25V/X7R/10%  [0402C]  184.67 130.41 0 top
LAB41  NC  [0402C]  184.16 -19.08 90 top
LAB42  NC  [0402C]  187.49 -19.08 90 top
LAB43  NC  [0402C]  184.16 -9.08 90 top
LAB44  NC  [0402C]  187.49 -9.08 90 top
LAB45  NC  [0402C]  184.16 0.92 90 top
LAB46  NC  [0402C]  187.49 0.92 90 top
LAB47  NC  [0402C]  184.16 10.92 90 top
LAB48  NC  [0402C]  187.49 10.92 90 top
LAB49  NC  [0402C]  184.16 20.92 90 top
LAB50  NC  [0402C]  187.49 20.92 90 top
LAB51  NC  [0402C]  184.16 30.92 90 top
LAB52  NC  [0402C]  187.49 30.92 90 top
LAB53  NC  [0402C]  184.16 40.92 90 top
LAB54  NC  [0402C]  187.49 40.92 90 top
LAB55  NC  [0402C]  184.16 50.92 90 top
LAB56  NC  [0402C]  187.49 50.92 90 top
LG1  10nH/300mA  [0603L]  231.01 -23.09 0 bottom
NOREF  -  []  153.77 145.85 0 top
NOREF#2  -  [unnamed#2]  164.49 142.42 270 top
NOREF#3  -  []  153.77 -34.49 90 top
NOREF#4  -  []  407.77 -34.49 90 top
NOREF#5  -  [unnamed#2]  165.91 -30.15 270 top
NOREF#6  -  []  153.77 -34.49 0 top
NOREF#7  -  []  202.39 23.83 90 top
NOREF#8  -  []  247.6 9.17 0 top
NOREF#9  -  [unnamed#2]  368.43 -30.23 270 top
NOREF#10  -  [unnamed#2]  165.91 -30.15 90 bottom
NOREF#11  -  [unnamed#2]  164.49 142.42 90 bottom
NOREF#12  -  [unnamed#2]  368.43 -30.23 90 bottom
P3  HOLE_D2p5  [HOLE_D2_5]  225.67 20.02 0 top
P4  HOLE_D2p5  [HOLE_D2_5]  220.17 20.02 0 top
P5  HOLE_D2p5  [HOLE_D2_5]  225.67 100.02 0 top
P7  HOLE_D2p5  [HOLE_D2_5]  324.66 100.02 0 top
P8  HOLE_D2p5  [HOLE_D2_5]  220.17 100.02 0 top
P9  HOLE_D2p5  [HOLE_D2_5]  377.91 48.28 0 top
P11  HOLE_D2p5  [HOLE_D2_5]  330.16 100.02 0 top
P12  HOLE_D2p5  [HOLE_D2_5]  330.16 20.02 0 top
P13  HOLE_D2p5  [HOLE_D2_5]  324.66 20.02 0 top
P14  HOLE_D2p5  [HOLE_D2_5]  353.35 -27.51 0 top
Q1  MMBT3904LT1G  [SOT_23]  282.98 -20.97 270 top
Q2  MMBT3904LT1G  [SOT_23]  291.85 -20.97 270 top
Q3  MMBT3904LT1G  [SOT_23]  300.71 -20.97 270 top
Q4  MMBT3904LT1G  [SOT_23]  309.58 -20.97 270 top
Q5  9014  [SOT_23]  354.42 64.9 180 top
Q6  9014  [SOT_23]  354.42 59.77 180 top
Q7  9014  [SOT_23]  354.38 54.64 180 top
R1  4.7K,1%  [R0402]  391.26 19.14 0 top
R2  4.7K,1%  [R0402]  394.56 25.16 135 bottom
R3  0R,1%  [R0402]  383.79 12.22 90 top
R4  12.1K,1%  [R0402]  391.85 2.11 180 top
R5  12.1K,1%  [R0402]  391.73 7.83 0 top
R6  0R,1%  [R0402]  392.17 12.22 90 top
R7  4.75K,1%  [R0402]  388.46 17.81 0 bottom
R8  4.75K,1%  [R0402]  385.67 17.81 0 bottom
R9  4.75K,1%  [R0402]  382.87 17.81 0 bottom
R10  4.75K,1%  [R0402]  391.26 17.81 0 bottom
R11  0R,1%  [R0402]  389.38 12.22 90 top
R12  0R,1%  [R0402]  386.58 12.22 90 top
R13  5.1K,1%  [R0402]  399.86 7.71 180 bottom
R14  0R,1%  [R0402]  381 12.22 90 top
R15  5.1K,1%  [R0402]  403.6 9.98 0 bottom
R16  0R,1%  [R0402]  378.2 12.22 90 top
R17  10K,1%  [R0402]  385.75 -3.61 180 bottom
R18  2.2K,1%  [0402R]  386.26 -3.44 270 top
R19  10K,1%  [R0402]  385.75 -1.6 180 bottom
R20  10K,1%  [R0402]  385.75 -2.6 180 bottom
R21  510R,1%  [R0402]  394.34 15.67 0 top
R22  RES,510,0402  [R0402]  286.84 -21.69 90 top
R23  RES,510R,0402  [R0402]  280.8 -21.95 270 top
R24  RES,510R,0402  [R0402]  283.61 -18.99 0 top
R25  RES,510,0402  [R0402]  295.71 -21.69 90 top
R26  RES,510R,0402  [R0402]  289.66 -21.95 270 top
R27  RES,510R,0402  [R0402]  292.47 -18.99 0 top
R28  RES,510,0402  [R0402]  304.57 -21.69 90 top
R29  RES,510R,0402  [R0402]  298.53 -21.95 270 top
R30  RES,510R,0402  [R0402]  301.34 -18.99 0 top
R31  RES,510,0402  [R0402]  313.44 -21.69 90 top
R32  RES,510R,0402  [R0402]  307.39 -21.95 270 top
R33  RES,510R,0402  [R0402]  310.2 -18.99 0 top
R34  4.75K,1%  [R0402]  362.79 86.73 0 bottom
R35  4.75K,1%  [R0402]  362.79 85.8 0 bottom
R36  4.75K,1%  [R0402]  362.43 81.28 270 bottom
R37  4.75K,1%  [R0402]  362.79 84.89 0 bottom
R38  4.75K,1%  [R0402]  353.64 84.37 270 bottom
R39  4.75K,1%  [R0402]  354.71 84.37 270 bottom
R40  4.75K,1%  [R0402]  350.88 80.49 270 top
R48  RES,2.37K 1%,0402  [R0402]  381.04 57.17 90 bottom
R49  RES,510,0402  [R0402]  403.75 53.18 270 bottom
R50  RES,510,0402  [R0402]  403.75 74.32 90 bottom
R62  510R,1%  [R0402]  324.44 6.29 270 bottom
R63  4.7K,1%  [R0402]  351.38 49.37 90 top
R64  4.7K,1%  [R0402]  334.83 -9.16 180 top
R66  4.7K,1%  [R0402]  382.02 42.81 0 bottom
R67  10K,1%  [R0402]  386.59 43.3 270 top
R68  8.06K 1%  [R0402]  384.58 43.3 270 top
R69  RES,1K,0402  [R0402]  385.6 43.3 270 top
R70  33R,1%  [R0402]  383.63 43.28 90 top
R72  260R,1%  [R0402]  382.73 32.23 0 top
R73  190R,1%  [R0402]  383.72 28.24 180 top
R74  510R,1%  [R0402]  352.15 62.52 180 top
R75  510R,1%  [R0402]  354.03 62.52 180 top
R76  0R,1%  [R0402]  214.07 -23.92 180 bottom
R77  33R,1%  [R0402]  212.02 -26.59 270 bottom
R78  510R,1%  [R0402]  352.15 57.38 180 top
R79  510R,1%  [R0402]  354.03 57.38 180 top
R80  510R,1%  [R0402]  352.15 52.25 180 top
R81  510R,1%  [R0402]  353.98 52.25 180 top
R82  0R,1%  [R0402]  215.87 -23.92 0 bottom
R83  33R,1%  [R0402]  217.93 -26.59 270 bottom
R84  499R,1%  [R0402]  395.15 -4.5 0 top
R85  499R,1%  [R0402]  395.15 -3.4 0 top
R86  499R,1%  [R0402]  356.82 69.03 180 top
R87  499R,1%  [R0402]  356.82 72.67 180 top
R88  33R,1%  [R0402]  266.34 -25.48 90 bottom
R89  0R,1%  [R0402]  266.34 -22.31 90 bottom
R90  50R,1%  [R0402]  266.74 -24.06 0 bottom
R91  33R,1%  [R0402]  259.45 -25.45 90 bottom
R92  50R,1%  [R0402]  259.84 -24.03 0 bottom
R93  33R,1%  [R0402]  252.55 -24.88 90 bottom
R94  240R,1%  [R0402]  252.15 -23.47 180 bottom
R95  4.99K,1%  [R0603]  364.49 44.16 0 bottom
R96  0R,1%  [R0603]  367.44 44.16 0 bottom
R97  0R,1%  [R0402]  362.7 46.58 90 bottom
R99  10K,1%  [R0603]  354.08 44.93 90 top
R100  2K,1%  [R0603]  309.74 111.96 270 top
R101  221R,1%  [R0603]  309.74 108.84 270 top
R102  0R,1%  [R0402]  311.34 112.72 0 top
R104  10K,1%  [R0603]  310.87 123.21 0 top
R184  4.75K,1%  [R0402]  375.57 127.62 0 bottom
R185  4.75K,1%  [R0402]  371.95 128.42 180 bottom
R186  4.75K,1%  [R0402]  375.57 128.67 0 bottom
R187  4.75K,1%  [R0402]  371.95 129.47 180 bottom
R188  4.75K,1%  [R0402]  375.57 129.73 0 bottom
R189  4.75K,1%  [R0402]  371.95 130.52 180 bottom
R190  4.75K,1%  [R0402]  371.95 131.57 180 bottom
R191  4.75K,1%  [R0402]  375.57 130.78 0 bottom
R208  4.7K,5%  [R0402]  341.24 35.69 180 top
R209  0R,5%  [R0402]  376.25 61.16 0 top
RAA2  0R  [0402R]  171.06 -17.85 0 top
RAA3  NC  [0402R]  169.73 -18.25 270 top
RAA4  NC  [0402R]  172.41 -18.25 270 top
RAA6  0R  [0402R]  171.06 -7.85 0 top
RAA7  NC  [0402R]  169.73 -8.25 270 top
RAA8  NC  [0402R]  172.41 -8.25 270 top
RAA10  0R  [0402R]  171.06 2.15 0 top
RAA11  NC  [0402R]  169.73 1.75 270 top
RAA12  NC  [0402R]  172.41 1.75 270 top
RAA14  0R  [0402R]  171.06 12.15 0 top
RAA15  NC  [0402R]  169.73 11.75 270 top
RAA16  NC  [0402R]  172.41 11.75 270 top
RAA18  0R  [0402R]  171.06 22.15 0 top
RAA19  NC  [0402R]  169.73 21.75 270 top
RAA20  NC  [0402R]  172.41 21.75 270 top
RAA22  0R  [0402R]  171.06 32.15 0 top
RAA23  NC  [0402R]  169.73 31.75 270 top
RAA24  NC  [0402R]  172.41 31.75 270 top
RAA26  0R  [0402R]  171.06 42.15 0 top
RAA27  NC  [0402R]  169.73 41.75 270 top
RAA28  NC  [0402R]  172.41 41.75 270 top
RAA30  0R  [0402R]  171.06 52.15 0 top
RAA31  NC  [0402R]  169.73 51.75 270 top
RAA32  NC  [0402R]  172.41 51.75 270 top
RAB2  0R  [0402R]  171.06 62.15 180 top
RAB3  NC  [0402R]  172.41 61.75 270 top
RAB4  NC  [0402R]  169.73 61.75 270 top
RAB6  0R  [0402R]  171.06 72.15 180 top
RAB7  NC  [0402R]  172.41 71.75 270 top
RAB8  NC  [0402R]  169.73 71.75 270 top
RAB10  0R  [0402R]  171.06 82.15 180 top
RAB11  NC  [0402R]  172.41 81.75 270 top
RAB12  NC  [0402R]  169.73 81.75 270 top
RAB14  0R  [0402R]  171.06 92.15 180 top
RAB15  NC  [0402R]  172.41 91.75 270 top
RAB16  NC  [0402R]  169.73 91.75 270 top
RAB18  0R  [0402R]  171.06 102.15 180 top
RAB19  NC  [0402R]  172.41 101.75 270 top
RAB20  NC  [0402R]  169.73 101.75 270 top
RAB22  0R  [0402R]  171.06 112.15 180 top
RAB23  NC  [0402R]  172.41 111.75 270 top
RAB24  NC  [0402R]  169.73 111.75 270 top
RAB26  0R  [0402R]  171.06 122.15 180 top
RAB27  NC  [0402R]  172.41 121.75 270 top
RAB28  NC  [0402R]  169.73 121.75 270 top
RAB30  0R  [0402R]  171.06 132.15 180 top
RAB31  NC  [0402R]  172.41 131.75 270 top
RAB32  NC  [0402R]  169.73 131.75 270 top
RG1  10R,5%  [R0603]  234.14 -22.33 270 bottom
RG2  33R,5%  [R0603]  232.54 -21.97 90 top
RG3  33,5%  [R0603]  233.95 -21.97 90 top
RL10  10K,5%  [0402R]  375.24 62.64 270 top
RL11  10K,5%  [0402R]  384.2 70.12 90 top
RL14  10K,5%  [0402R]  381.2 70.12 90 top
RL15  10K,5%  [0402R]  382.2 70.12 90 top
RL16  10K,5%  [0402R]  380.2 70.12 90 top
RL17  10K,5%  [0402R]  377.2 70.12 90 top
RL18  10K,5%  [0402R]  383.2 70.12 90 top
RL19  10K,5%  [0402R]  379.2 70.12 90 top
RL20  10K,5%  [0402R]  378.2 70.12 90 top
RL21  10K,5%  [0402R]  376.2 70.12 90 top
RP1  2K 1%  [0402R]  238.46 129.1 90 bottom
RP2  0R 1%  [0402R]  237.49 129.1 270 bottom
RP3  0R, 1%  [0402R]  232.19 126.81 45 bottom
RP4  0R, 1%  [0402R]  236 126.81 45 bottom
RP5  0R, 1%  [0402R]  241.13 126.79 45 bottom
RP6  0R, 1%  [0402R]  242.13 130.47 270 bottom
RP7  0R, 1%  [0402R]  232.87 123.59 270 bottom
RP8  0R, 1%  [0402R]  234 123.59 270 bottom
RP9  0R, 1%  [0402R]  238.07 121.46 270 bottom
RP10  100K 1%  [0402R]  242.06 123.99 180 bottom
RP11  0R, 1%  [0402R]  241.66 122.07 270 bottom
RP12  10K 1%  [0402R]  236.02 122 90 bottom
RP129  1K,1%  [0402R]  308.56 138.16 90 bottom
SP1  HEADER 2  [SIP2_HV]  300.5 142.48 270 top
SWC1  -  [A6FR-2104]  402.77 -2.86 90 top
SWC2  -  [SIP2]  351.55 69.04 0 top
SWC3  -  [SIP2]  351.55 72.17 0 top
SWC4  -  [SWP1]  405.36 -14.05 90 top
TAB1  TCM2-63WX+  [TCM1-63AX_]  179.12 60.88 90 top
TAB2  TCM2-63WX+  [TCM1-63AX_]  179.12 70.88 90 top
TAB3  TCM2-63WX+  [TCM1-63AX_]  179.12 80.88 90 top
TAB4  TCM2-63WX+  [TCM1-63AX_]  179.12 90.88 90 top
TAB5  TCM2-63WX+  [TCM1-63AX_]  179.12 100.88 90 top
TAB6  TCM2-63WX+  [TCM1-63AX_]  179.12 110.88 90 top
TAB7  TCM2-63WX+  [TCM1-63AX_]  179.12 120.88 90 top
TAB8  TCM2-63WX+  [TCM1-63AX_]  179.12 130.88 90 top
TAB9  TCM2-63WX+  [TCM1-63AX_]  179.12 -19.12 90 top
TAB10  TCM2-63WX+  [TCM1-63AX_]  179.12 -9.12 90 top
TAB11  TCM2-63WX+  [TCM1-63AX_]  179.12 0.88 90 top
TAB12  TCM2-63WX+  [TCM1-63AX_]  179.12 10.88 90 top
TAB13  TCM2-63WX+  [TCM1-63AX_]  179.12 20.88 90 top
TAB14  TCM2-63WX+  [TCM1-63AX_]  179.12 30.88 90 top
TAB15  TCM2-63WX+  [TCM1-63AX_]  179.12 40.88 90 top
TAB16  TCM2-63WX+  [TCM1-63AX_]  179.12 50.88 90 top
TP1  PGOOD1  [PAD-50SMT]  238.07 123.99 270 bottom
U2  FT2232HQ  [QFN64]  384.33 3.86 90 top
U3  SN74AVC1T45DCK  [SC70_6]  383.13 15.16 90 top
U4  SN74AVC1T45DCK  [SC70_6]  391.52 15.16 90 top
U5  SN74AVC1T45DCK  [SC70_6]  388.72 15.16 90 top
U6  SN74AVC1T45DCK  [SC70_6]  385.93 15.16 90 top
U7  SN74AVC1T45DCK  [SC70_6]  380.34 15.16 90 top
U8  SN74AVC1T45DCK  [SC70_6]  377.55 15.16 90 top
U9  SPX3819M5-L-3-3  [SOT_25]  394.82 0.79 0 top
U10  93LC56BT-I/ST  [TSSOP8]  381.89 -4.38 90 top
U12  AR8035-AL1A  [QFN40]  380.44 64.21 0 top
U13  SN65LVDS104PWR  [TSSOP16]  343.01 30.58 180 top
U15  USB3320C-EZK  [QFN32]  382.3 38.81 0 top
U17  MIC2544-1BM  [SO_8]  388.94 30.15 0 top
U18  RCLAMP0524J  [TVS_0524J]  386.64 51.05 270 top
U19  LTM4644EY#PBF  [4644_BGA]  237.3 124.25 90 top
U20  MYMGK00504ERSR  [LGA_75]  359.12 44.16 180 top
U21  MYMGK00504ERSR  [LGA_75]  309.74 117.95 90 top
U22  -  [BNX016-01]  365.96 3.3 180 top
UG1  -  [NEO-M8N]  230.44 -12.32 90 top
X1  24.000MHz  [XTALSMD_3225]  385.47 46.28 180 top
XS1  SIT9121AI-2B3-33E156.25  [XTALSMD_3225_DP]  342.97 24.43 90 top
XS2  SIT9121AI-2B3-33E100  [XTALSMD_3225_DP]  352 30.67 0 top
Y1  12.000MHz  [CRYSTAL_5X3P2]  391.01 -4.55 180 top
Y2  25.000MHz  [CRYSTAL_5X3P2]  378.26 55.59 0 top
Y7  SIT9121AI-2B3-33S-52  [XTALSMD_3225_DP]  341.08 38.82 90 top

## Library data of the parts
C1-C48 C53 C57 C58 C78-C81 C84-C98 C101-C104 C108-C110 C288-C290 CAA4 CAA9 CAA14 CAA19 CAA24 CAA29 CAA34 CAA39 CAB4 CAB6 CAB10 CAB12 CAB16 CAB18 CAB22 CAB24 CAB28 CAB30 CAB34 CAB36 CAB40 CAB42 CAB46 CAB48-CAB76 CG1-CG3 CL7-CL15 CL17 CL18 = CAP
C68-C77 = CAP: signal model: CAP_C0402_0.1UF/25V/X7R/10%_0.1uF/25V/X7R/10%
C105-C107 CIN1-CIN4 CIN7 CIN8 CIN10 CIN11 COUT1-COUT5 COUT9-COUT14 = CAP1206
CIN5 CIN6 CIN9 = CAP-SVPA-E7
D1 D2 D14 D16 = SCHOTTKY,BAT54S
D3 = LED,GREEN,0603
D4-D8 D11-D13 D15 = LED
D9 D10 = 40CPQ045/TO_0
D19 = DIODE TVS
EC1 = 16SVPK330M
FB1 FB2 = BLM18PG181SN1D
FB3-FB7 FB9 FB12-FB14 = BLM21PG121SN1D
FB15 = JK250-800U
FBA1 FBA2 = BLM18PG221SN1
FBL1-FBL3 LG1 = INDUCTOR
FBP1 FBP2 FBP7-FBP10 FBP17-FBP20 = BLM21PG121SN1
H7-H48 = HOLE
J1 = LPAF_50_03_L_08_2_TR_17: User Part Number: NCAB; Tolerance: #TOL
J2 = LPAM_50_01_L_08_7: User Part Number: NCAB; Tolerance: #TOL
J3 = mini sd_1
J4 = USB-TYPEC
J5-J8 J19-J22 J24 J25 J27 J28 JFA6 = HX-TJC3-2PIN-WHITE
J9 = HEADER 10
J10 J11 = JST_2p0_15
J12 = QSFP28-FS1-Z38-20Z6-20_0
J13 = U95-T1A1-101A
J16 = HR911130C
J17 = M_2_SLOT
J18 = USB3-A
J23 = POWER_JACK_ADAPTER
J26 = POWER HEADER-6P-4P2MM_0
J32 = 022112032
J40 = SFP+_SINGLEMODULE
JA1-JA22 = BNC_3
JU1 = USB-MICRO-VAR
LAB2-LAB4 LAB7-LAB9 LAB12-LAB14 LAB17-LAB19 LAB22-LAB24 LAB27-LAB29 LAB32-LAB34 LAB37-LAB39 LAB41-LAB56 R14 R16 R18 R23 R24 R26 R27 R29 R30 R32-R40 R101 R102 R104 RAA2-RAA4 RAA6-RAA8 RAA10-RAA12 RAA14-RAA16 RAA18-RAA20 RAA22-RAA24 RAA26-RAA28 RAA30-RAA32 RAB2-RAB4 RAB6-RAB8 RAB10-RAB12 RAB14-RAB16 RAB18-RAB20 RAB22-RAB24 RAB26-RAB28 RAB30-RAB32 RG1-RG3 RL10 RL11 RL14-RL21 RP129 = RES
P3-P5 P7-P9 P11-P14 = HOLE_2p5
Q1-Q4 = MMBT3904LT1G
Q5-Q7 = 1R1001_0
R1-R13 R15 R17 R19-R22 R25 R28 R31 R48-R50 R62-R64 R66-R70 R72-R76 R78-R82 R84-R87 R184-R191 R208 R209 = RES-H
R77 R83 R88-R94 = RES,33R,0402
R95-R97 R99 R100 = RES: signal model: RES-H_R0402-BGA_33R_33R
RP1-RP12 = R
SP1 = HEADER 2
SWC1 = A6FR-2104
SWC2 SWC3 = B2S_0
SWC4 = SW_PB_SPST
TAB1-TAB16 = TCM1_83X_P_1
TP1 = E-100SMT: Tolerance: #TOL; User Part Number: NCAB
U2 = FT2232HQ
U3-U8 = SN74AVC1T45
U9 = SPX3819M5-L-3-3
U10 = 93LC56BT-I/ST
U12 = AR8035-AL1A
U13 = SN65LVDS105
U15 = USB3320C-EZK
U17 = MIC2025-1BM
U18 = RCLAMP0524J
U19 = LTM4644EY#PBF_2: Tolerance: #TOL; User Part Number: NCAB
U20 U21 = MYMGK00504ERSR_1
U22 = BNX016-01
UG1 = NEO-M8N
X1 = XTAL
XS1 XS2 = SIT9121: User Part Number: NCAB; Tolerance: #TOL
Y1 Y2 = CRYSTAL
Y7 = SIT9121AI-2D2-33E200.000000X: User Part Number: NCAB; Tolerance: #TOL

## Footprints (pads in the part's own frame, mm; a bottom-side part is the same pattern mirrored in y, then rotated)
0402C
  rect 0.635x0.508 smd: 1(-0.508,0) 2(0.508,0)
0402R
  rect 0.5x0.5 smd: 1(-0.399,0) 2(0.399,0)
0603L
  rect 0.889x0.889 smd: 1(0.762,0) 2(-0.762,0)
0603LED
  rect 0.813x0.991 smd: 1(-0.775,0) 2(0.775,0)
0805L
  rect 1.016x1.27 smd: 1(-1.016,0) 2(1.016,0)
4644_BGA
  round 0.635 smd: A1(-3.81,6.35) A2(-2.54,6.35) A3(-1.27,6.35) A4(0,6.35) A5(1.27,6.35) A6(2.54,6.35) A7(3.81,6.35) B1(-3.81,5.08) B2(-2.54,5.08) B3(-1.27,5.08) B4(0,5.08) B5(1.27,5.08) B6(2.54,5.08) B7(3.81,5.08) C1(-3.81,3.81) C2(-2.54,3.81) C3(-1.27,3.81) C4(0,3.81) C5(1.27,3.81) C6(2.54,3.81) C7(3.81,3.81) D1(-3.81,2.54) D2(-2.54,2.54) D3(-1.27,2.54) D4(0,2.54) D5(1.27,2.54) D6(2.54,2.54) D7(3.81,2.54) E1(-3.81,1.27) E2(-2.54,1.27) E3(-1.27,1.27) E4(0,1.27) E5(1.27,1.27) E6(2.54,1.27) E7(3.81,1.27) F1(-3.81,0) F2(-2.54,0) F3(-1.27,0) F4(0,0) F5(1.27,0) F6(2.54,0) F7(3.81,0) G1(-3.81,-1.27) G2(-2.54,-1.27) G3(-1.27,-1.27) G4(0,-1.27) G5(1.27,-1.27) G6(2.54,-1.27) G7(3.81,-1.27) H1(-3.81,-2.54) H2(-2.54,-2.54) H3(-1.27,-2.54) H4(0,-2.54) H5(1.27,-2.54) H6(2.54,-2.54) H7(3.81,-2.54) J1(-3.81,-3.81) J2(-2.54,-3.81) J3(-1.27,-3.81) J4(0,-3.81) J5(1.27,-3.81) J6(2.54,-3.81) J7(3.81,-3.81) K1(-3.81,-5.08) K2(-2.54,-5.08) K3(-1.27,-5.08) K4(0,-5.08) K5(1.27,-5.08) K6(2.54,-5.08) K7(3.81,-5.08) L1(-3.81,-6.35) L2(-2.54,-6.35) L3(-1.27,-6.35) L4(0,-6.35) L5(1.27,-6.35) L6(2.54,-6.35) L7(3.81,-6.35)
7343-43
  rect 2.413x2.413 smd: 1(-3.134,0) 2(3.134,0)
7343FUSE
  rect 2.591x2.388 smd: 1(-3.205,0) 2(3.205,0)
022112032
  rect 1.524x1.524 hole 1.016: 1(0,0)
  round 1.524 hole 1.016: 2(0,-2.54) 3(0,-5.08)
2012670005
  rect 0.3x0.7 smd: A1(-3,0.85) A2(-2.5,0.85) A3(-2,0.85) A4(-1.5,0.85) A5(-1,0.85) A6(-0.5,0.85) A7(0.5,0.85) A8(1,0.85) A9(1.5,0.85) A10(2,0.85) A11(2.5,0.85) A12(3,0.85) B2(2.25,-0.85) B3(1.75,-0.85) B4(1.25,-0.85) B5(0.75,-0.85) B6(0.25,-0.85) B7(-0.25,-0.85) B8(-0.75,-0.85) B9(-1.25,-0.85) B10(-1.75,-0.85) B11(-2.25,-0.85)
  rect 0.9x0.7 smd: B1(3.05,-0.85) B12(-3.05,-0.85)
  oval 1.1x2.1 hole 0.6x1.6: SH1(-4.32,0.04) SH2(4.32,0.04)
  oval 1.1x3.6 hole 0.6x2.1: SH3(-4.62,-5.32) SH4(4.62,-5.32)
A6FR-2104
  rect 1.4x1.4 hole 1: 1(-1.27,-3.81)
  round 1.4 hole 1: 2(-1.27,3.81) 3(1.27,-3.81) 4(1.27,3.81)
BNX016-01
  rect 1.829x1.829 hole 1.219: 1(1.25,2.499)
  round 1.829 hole 1.219: 3(-3.749,2.499) 5(-3.749,-2.499) 6(-1.25,0) 7(3.749,0) 8(1.25,-2.499)
C0402
  rect 0.635x0.508 smd: 1(-0.508,0) 2(0.508,0)
C0402-BGA
  round 0.635 smd: 1(-0.5,0) 2(0.5,0)
C0603
  rect 0.889x0.813 smd: 1(-0.762,0) 2(0.762,0)
C1206
  rect 1.397x1.651 smd: 1(-1.397,0) 2(1.397,0)
CRYSTAL_5X3P2
  rect 1.702x2.388 smd: 1(-1.849,0) 2(1.849,0)
EC-E7
  rect 3.937x1.524 smd: 1(-3.15,0) 2(3.15,0)
FB0805
  rect 0.95x1.3 smd: 1(-0.874,0) 2(0.874,0)
HOLE
  round 5.994 hole 3.505: 1(0,0)
  round 0.813 hole 0.508: 2(0.114,2.367) 3(1.765,1.656) 4(2.451,0.107) 5(1.765,-1.646) 6(0.089,-2.383) 7(-1.638,-1.621) 8(-2.299,0.107) 9(-1.689,1.681)
HOLE_D2_5
  round 2.997 hole 2.515: 1(0,0)
HR911130C
  round 3.2 hole 3.2 unplated: (-11.43,8.89) (0,8.89)
  round 1.6 hole 1.016: 1(0,0) 2(-1.27,2.54) 3(-2.54,0) 4(-3.81,2.54) 5(-5.08,0) 6(-6.35,2.54) 7(-7.62,0) 8(-8.89,2.54) 9(-10.16,0) 10(-11.43,2.54)
  round 1.6 hole 1.219: 11(0.909,13.79) 12(-1.631,13.79) 13(-9.799,13.79) 14(-12.339,13.79)
  round 2.388 hole 1.651: 15(2.029,5.839) 16(-13.459,5.839)
HX-TJC3-2PIN-WHITE
  round 1.524 hole 1.016: 1(1.25,0) 2(-1.25,0)
LED-0603
  rect 0.8x0.8 smd: 1(0.749,0) 2(-0.749,0)
LGA_75
  rect 1.016x1.397 smd: 1(-2.751,3.551) 2(-1.199,3.551) 6(-2.751,-3.551) 7(-1.199,-3.551) 8(1.199,-3.551) 9(2.751,-3.551) 13(2.751,3.551) 14(1.199,3.551)
  rect 1x0.9 smd: 3(-2.751,1.199) 4(-2.751,0) 5(-2.751,-1.199) 10(2.751,-1.199) 11(2.751,0) 12(2.751,1.199) 15(-1.199,1.199) 16(-1.199,0) 17(-1.199,-1.199) 18(0,1.199) 19(0,0) 20(0,-1.199) 21(1.199,1.199) 22(1.199,0) 23(1.199,-1.199)
LPAM_50_01_TR
  round 1.448 hole 1.448 unplated: (-33.3,0) (33.3,2.03)
  round 0.635 smd: A1(-31.115,4.75) A2(-29.845,4.75) A3(-28.575,4.75) A4(-27.305,4.75) A5(-26.035,4.75) A6(-24.765,4.75) A7(-23.495,4.75) A8(-22.225,4.75) A9(-20.955,4.75) A10(-19.685,4.75) A11(-18.415,4.75) A12(-17.145,4.75) A13(-15.875,4.75) A14(-14.605,4.75) A15(-13.335,4.75) A16(-12.065,4.75) A17(-10.795,4.75) A18(-9.525,4.75) A19(-8.255,4.75) A20(-6.985,4.75) A21(-5.715,4.75) A22(-4.445,4.75) A23(-3.175,4.75) A24(-1.905,4.75) A25(-0.635,4.75) A26(0.635,4.75) A27(1.905,4.75) A28(3.175,4.75) A29(4.445,4.75) A30(5.715,4.75) A31(6.985,4.75) A32(8.255,4.75) A33(9.525,4.75) A34(10.795,4.75) A35(12.065,4.75) A36(13.335,4.75) A37(14.605,4.75) A38(15.875,4.75) A39(17.145,4.75) A40(18.415,4.75) A41(19.685,4.75) A42(20.955,4.75) A43(22.225,4.75) A44(23.495,4.75) A45(24.765,4.75) A46(26.035,4.75) A47(27.305,4.75) A48(28.575,4.75) A49(29.845,4.75) A50(31.115,4.75) B1(-31.115,3.48) B2(-29.845,3.48) B3(-28.575,3.48) B4(-27.305,3.48) B5(-26.035,3.48) B6(-24.765,3.48) B7(-23.495,3.48) B8(-22.225,3.48) B9(-20.955,3.48) B10(-19.685,3.48) B11(-18.415,3.48) B12(-17.145,3.48) B13(-15.875,3.48) B14(-14.605,3.48) B15(-13.335,3.48) B16(-12.065,3.48) B17(-10.795,3.48) B18(-9.525,3.48) B19(-8.255,3.48) B20(-6.985,3.48) B21(-5.715,3.48) B22(-4.445,3.48) B23(-3.175,3.48) B24(-1.905,3.48) B25(-0.635,3.48) B26(0.635,3.48) B27(1.905,3.48) B28(3.175,3.48) B29(4.445,3.48) B30(5.715,3.48) B31(6.985,3.48) B32(8.255,3.48) B33(9.525,3.48) B34(10.795,3.48) B35(12.065,3.48) B36(13.335,3.48) B37(14.605,3.48) B38(15.875,3.48) B39(17.145,3.48) B40(18.415,3.48) B41(19.685,3.48) B42(20.955,3.48) B43(22.225,3.48) B44(23.495,3.48) B45(24.765,3.48) B46(26.035,3.48) B47(27.305,3.48) B48(28.575,3.48) B49(29.845,3.48) B50(31.115,3.48) C1(-31.115,2.21) C2(-29.845,2.21) C3(-28.575,2.21) C4(-27.305,2.21) C5(-26.035,2.21) C6(-24.765,2.21) C7(-23.495,2.21) C8(-22.225,2.21) C9(-20.955,2.21) C10(-19.685,2.21) C11(-18.415,2.21) C12(-17.145,2.21) C13(-15.875,2.21) C14(-14.605,2.21) C15(-13.335,2.21) C16(-12.065,2.21) C17(-10.795,2.21) C18(-9.525,2.21) C19(-8.255,2.21) C20(-6.985,2.21) C21(-5.715,2.21) C22(-4.445,2.21) C23(-3.175,2.21) C24(-1.905,2.21) C25(-0.635,2.21) C26(0.635,2.21) C27(1.905,2.21) C28(3.175,2.21) C29(4.445,2.21) C30(5.715,2.21) C31(6.985,2.21) C32(8.255,2.21) C33(9.525,2.21) C34(10.795,2.21) C35(12.065,2.21) C36(13.335,2.21) C37(14.605,2.21) C38(15.875,2.21) C39(17.145,2.21) C40(18.415,2.21) C41(19.685,2.21) C42(20.955,2.21) C43(22.225,2.21) C44(23.495,2.21) C45(24.765,2.21) C46(26.035,2.21) C47(27.305,2.21) C48(28.575,2.21) C49(29.845,2.21) C50(31.115,2.21) D1(-31.115,0.94) D2(-29.845,0.94) D3(-28.575,0.94) D4(-27.305,0.94) D5(-26.035,0.94) D6(-24.765,0.94) D7(-23.495,0.94) D8(-22.225,0.94) D9(-20.955,0.94) D10(-19.685,0.94) D11(-18.415,0.94) D12(-17.145,0.94) D13(-15.875,0.94) D14(-14.605,0.94) D15(-13.335,0.94) D16(-12.065,0.94) D17(-10.795,0.94) D18(-9.525,0.94) D19(-8.255,0.94) D20(-6.985,0.94) D21(-5.715,0.94) D22(-4.445,0.94) D23(-3.175,0.94) D24(-1.905,0.94) D25(-0.635,0.94) D26(0.635,0.94) D27(1.905,0.94) D28(3.175,0.94) D29(4.445,0.94) D30(5.715,0.94) D31(6.985,0.94) D32(8.255,0.94) D33(9.525,0.94) D34(10.795,0.94) D35(12.065,0.94) D36(13.335,0.94) D37(14.605,0.94) D38(15.875,0.94) D39(17.145,0.94) D40(18.415,0.94) D41(19.685,0.94) D42(20.955,0.94) D43(22.225,0.94) D44(23.495,0.94) D45(24.765,0.94) D46(26.035,0.94) D47(27.305,0.94) D48(28.575,0.94) D49(29.845,0.94) D50(31.115,0.94) E1(-31.115,-0.33) E2(-29.845,-0.33) E3(-28.575,-0.33) E4(-27.305,-0.33) E5(-26.035,-0.33) E6(-24.765,-0.33) E7(-23.495,-0.33) E8(-22.225,-0.33) E9(-20.955,-0.33) E10(-19.685,-0.33) E11(-18.415,-0.33) E12(-17.145,-0.33) E13(-15.875,-0.33) E14(-14.605,-0.33) E15(-13.335,-0.33) E16(-12.065,-0.33) E17(-10.795,-0.33) E18(-9.525,-0.33) E19(-8.255,-0.33) E20(-6.985,-0.33) E21(-5.715,-0.33) E22(-4.445,-0.33) E23(-3.175,-0.33) E24(-1.905,-0.33) E25(-0.635,-0.33) E26(0.635,-0.33) E27(1.905,-0.33) E28(3.175,-0.33) E29(4.445,-0.33) E30(5.715,-0.33) E31(6.985,-0.33) E32(8.255,-0.33) E33(9.525,-0.33) E34(10.795,-0.33) E35(12.065,-0.33) E36(13.335,-0.33) E37(14.605,-0.33) E38(15.875,-0.33) E39(17.145,-0.33) E40(18.415,-0.33) E41(19.685,-0.33) E42(20.955,-0.33) E43(22.225,-0.33) E44(23.495,-0.33) E45(24.765,-0.33) E46(26.035,-0.33) E47(27.305,-0.33) E48(28.575,-0.33) E49(29.845,-0.33) E50(31.115,-0.33) F1(-31.115,-1.6) F2(-29.845,-1.6) F3(-28.575,-1.6) F4(-27.305,-1.6) F5(-26.035,-1.6) F6(-24.765,-1.6) F7(-23.495,-1.6) F8(-22.225,-1.6) F9(-20.955,-1.6) F10(-19.685,-1.6) F11(-18.415,-1.6) F12(-17.145,-1.6) F13(-15.875,-1.6) F14(-14.605,-1.6) F15(-13.335,-1.6) F16(-12.065,-1.6) F17(-10.795,-1.6) F18(-9.525,-1.6) F19(-8.255,-1.6) F20(-6.985,-1.6) F21(-5.715,-1.6) F22(-4.445,-1.6) F23(-3.175,-1.6) F24(-1.905,-1.6) F25(-0.635,-1.6) F26(0.635,-1.6) F27(1.905,-1.6) F28(3.175,-1.6) F29(4.445,-1.6) F30(5.715,-1.6) F31(6.985,-1.6) F32(8.255,-1.6) F33(9.525,-1.6) F34(10.795,-1.6) F35(12.065,-1.6) F36(13.335,-1.6) F37(14.605,-1.6) F38(15.875,-1.6) F39(17.145,-1.6) F40(18.415,-1.6) F41(19.685,-1.6) F42(20.955,-1.6) F43(22.225,-1.6) F44(23.495,-1.6) F45(24.765,-1.6) F46(26.035,-1.6) F47(27.305,-1.6) F48(28.575,-1.6) F49(29.845,-1.6) F50(31.115,-1.6) G1(-31.115,-2.87) G2(-29.845,-2.87) G3(-28.575,-2.87) G4(-27.305,-2.87) G5(-26.035,-2.87) G6(-24.765,-2.87) G7(-23.495,-2.87) G8(-22.225,-2.87) G9(-20.955,-2.87) G10(-19.685,-2.87) G11(-18.415,-2.87) G12(-17.145,-2.87) G13(-15.875,-2.87) G14(-14.605,-2.87) G15(-13.335,-2.87) G16(-12.065,-2.87) G17(-10.795,-2.87) G18(-9.525,-2.87) G19(-8.255,-2.87) G20(-6.985,-2.87) G21(-5.715,-2.87) G22(-4.445,-2.87) G23(-3.175,-2.87) G24(-1.905,-2.87) G25(-0.635,-2.87) G26(0.635,-2.87) G27(1.905,-2.87) G28(3.175,-2.87) G29(4.445,-2.87) G30(5.715,-2.87) G31(6.985,-2.87) G32(8.255,-2.87) G33(9.525,-2.87) G34(10.795,-2.87) G35(12.065,-2.87) G36(13.335,-2.87) G37(14.605,-2.87) G38(15.875,-2.87) G39(17.145,-2.87) G40(18.415,-2.87) G41(19.685,-2.87) G42(20.955,-2.87) G43(22.225,-2.87) G44(23.495,-2.87) G45(24.765,-2.87) G46(26.035,-2.87) G47(27.305,-2.87) G48(28.575,-2.87) G49(29.845,-2.87) G50(31.115,-2.87) H1(-31.115,-4.14) H2(-29.845,-4.14) H3(-28.575,-4.14) H4(-27.305,-4.14) H5(-26.035,-4.14) H6(-24.765,-4.14) H7(-23.495,-4.14) H8(-22.225,-4.14) H9(-20.955,-4.14) H10(-19.685,-4.14) H11(-18.415,-4.14) H12(-17.145,-4.14) H13(-15.875,-4.14) H14(-14.605,-4.14) H15(-13.335,-4.14) H16(-12.065,-4.14) H17(-10.795,-4.14) H18(-9.525,-4.14) H19(-8.255,-4.14) H20(-6.985,-4.14) H21(-5.715,-4.14) H22(-4.445,-4.14) H23(-3.175,-4.14) H24(-1.905,-4.14) H25(-0.635,-4.14) H26(0.635,-4.14) H27(1.905,-4.14) H28(3.175,-4.14) H29(4.445,-4.14) H30(5.715,-4.14) H31(6.985,-4.14) H32(8.255,-4.14) H33(9.525,-4.14) H34(10.795,-4.14) H35(12.065,-4.14) H36(13.335,-4.14) H37(14.605,-4.14) H38(15.875,-4.14) H39(17.145,-4.14) H40(18.415,-4.14) H41(19.685,-4.14) H42(20.955,-4.14) H43(22.225,-4.14) H44(23.495,-4.14) H45(24.765,-4.14) H46(26.035,-4.14) H47(27.305,-4.14) H48(28.575,-4.14) H49(29.845,-4.14) H50(31.115,-4.14)
M2_2422
  round 1.6 hole 1.6 unplated: (-19.26,5.285)
  round 6.02 hole 3.81: (-9.26,83.536) (-9.26,63.536) (-9.26,45.536)
  round 1.092 hole 1.092 unplated: (0.74,5.285)
  rect 0.279x1.549 smd: 1(-0.01,0.01) 2(-0.26,7.561) 3(-0.51,0.01) 4(-0.76,7.561) 5(-1.01,0.01) 6(-1.26,7.561) 7(-1.51,0.01) 8(-1.76,7.561) 9(-2.01,0.01) 10(-2.26,7.561) 11(-2.51,0.01) 12(-2.76,7.561) 13(-3.01,0.01) 14(-3.26,7.561) 15(-3.51,0.01) 16(-3.76,7.561) 17(-4.01,0.01) 18(-4.26,7.561) 19(-4.51,0.01) 20(-4.76,7.561) 21(-5.01,0.01) 22(-5.26,7.561) 23(-5.51,0.01) 24(-5.76,7.561) 25(-6.01,0.01) 26(-6.26,7.561) 27(-6.51,0.01) 28(-6.76,7.561) 29(-7.01,0.01) 30(-7.26,7.561) 31(-7.51,0.01) 32(-7.76,7.561) 33(-8.01,0.01) 34(-8.26,7.561) 35(-8.51,0.01) 36(-8.76,7.561) 37(-9.01,0.01) 38(-9.26,7.561) 39(-9.51,0.01) 40(-9.76,7.561) 41(-10.01,0.01) 42(-10.26,7.561) 43(-10.51,0.01) 44(-10.76,7.561) 45(-11.01,0.01) 46(-11.26,7.561) 47(-11.51,0.01) 48(-11.76,7.561) 49(-12.01,0.01) 50(-12.26,7.561) 51(-12.51,0.01) 52(-12.76,7.561) 53(-13.01,0.01) 54(-13.26,7.561) 55(-13.51,0.01) 56(-13.76,7.561) 57(-14.01,0.01) 58(-14.26,7.561) 67(-16.51,0.01) 68(-16.76,7.561) 69(-17.01,0.01) 70(-17.26,7.561) 71(-17.51,0.01) 72(-17.76,7.561) 73(-18.01,0.01) 74(-18.26,7.561) 75(-18.51,0.01)
  rect 1.194x2.743 smd: 76(1.09,0.785) 77(-19.61,0.785)
MMCX-TH1
  round 1.295 hole 0.864: 1(0,-1.27) 2(-1.27,-2.54) 3(1.27,0) 4(1.27,-2.54) 5(-1.27,0)
NEO-M8N
  rect 1.8x0.8 smd: 1(6,-7) 2(6,-5.9) 3(6,-4.8) 4(6,-3.7) 5(6,-2.6) 6(6,-1.5) 7(6,-0.4) 8(6,2.6) 9(6,3.7) 10(6,4.8) 11(6,5.9) 12(6,7) 13(-6,7) 14(-6,5.9) 15(-6,4.8) 16(-6,3.7) 17(-6,2.6) 18(-6,-0.4) 19(-6,-1.5) 20(-6,-2.6) 21(-6,-3.7) 22(-6,-4.8) 23(-6,-5.9) 24(-6,-7)
PAD-50SMT
  round 1.27 smd: 1(0,0)
POWER_HEADER-6P-4P2MM
  round 2.794 hole 1.803: 1(0,0) 2(0,-4.2) 3(0,-8.4) 4(-5.5,0) 5(-5.5,-4.2) 6(-5.5,-8.4)
  round 3.937 hole 3.175: 7(7.283,-0.009) 8(7.283,-8.391)
POWERA
  rect 3.2x3.2 hole 2.515: 1(0.001,0.009)
  oval 3.505x2.007 hole 2.845x1.524: 2(3.252,4.555)
  round 3.2 hole 2.515: 3(6.605,-0.093)
QFN32
  oval 0.711x0.254 smd: 1(-2.449,1.75) 2(-2.449,1.25) 3(-2.449,0.749) 4(-2.449,0.249) 5(-2.449,-0.249) 6(-2.449,-0.749) 7(-2.449,-1.25) 8(-2.449,-1.75) 17(2.451,-1.75) 18(2.451,-1.25) 19(2.451,-0.749) 20(2.451,-0.249) 21(2.451,0.249) 22(2.451,0.749) 23(2.451,1.25) 24(2.451,1.75)
  oval 0.254x0.711 smd: 9(-1.75,-2.449) 10(-1.25,-2.449) 11(-0.749,-2.449) 12(-0.249,-2.449) 13(0.249,-2.449) 14(0.749,-2.449) 15(1.25,-2.449) 16(1.75,-2.449) 25(1.75,2.451) 26(1.25,2.451) 27(0.749,2.451) 28(0.249,2.451) 29(-0.249,2.451) 30(-0.749,2.451) 31(-1.25,2.451) 32(-1.75,2.451)
  rect 3.302x3.302 smd: 33(0,0)
